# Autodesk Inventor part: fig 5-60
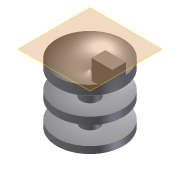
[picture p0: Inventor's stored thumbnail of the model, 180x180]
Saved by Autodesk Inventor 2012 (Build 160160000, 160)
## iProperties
Created: 2004-05
Part Number: fig 5-60
Document SubType Name: Modeling
Designer: CADCIM Technologies
Manufacturer: Standard
Standards Organization: Custom
Density: 1 g/cm^3
Material: Default
Author: CADCIM Technologies
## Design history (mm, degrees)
sketch "Sketch1"
  geometry: L1 (0.098, 22.743)-(0.098, 0.516); L2 (-3.621, 19.305)-(-3.621, 13.061); L3 (-3.621, 10.379)-(-3.621, 3.25); L4 (-3.664, 0.516)-(0.098, 0.516); L5 (-13.694, 4.7)-(-13.694, 1.836); L6 (-13.694, 26.851)-(-13.694, 23.014); L7 (-13.694, 15.335)-(-13.694, 12.343); A1 r 10.546 centre (-4.597, 32.185) between (-13.694, 26.851) and (0.098, 22.743); A2 r 21.828 centre (-4.597, 32.185) between (-13.694, 12.343) and (-3.621, 10.379); A3 r 12.918 centre (-4.597, 32.185) between (-13.694, 23.014) and (-3.621, 19.305); A4 r 19.149 centre (-4.597, 32.185) between (-13.694, 15.335) and (-3.621, 13.061); A5 r 28.952 centre (-4.597, 32.185) between (-13.694, 4.7) and (-3.621, 3.25); A6 r 31.683 centre (-4.597, 32.185) between (-13.694, 1.836) and (-3.664, 0.516)
  constraints: 14 end point, 12 point on circle, 6 centre point, 4 perpendicular, 2 parallel, 1 vertical
revolve "Revolution1" sketch "Sketch1" stored, may be unused: angle "d0" = 90 deg
workplane "Work Plane1"
sketch "Sketch2"
  geometry: L1 (3.408, -2.846)-(12.06, -2.846); L2 (12.06, -2.846)-(12.06, 2.873); L3 (12.06, 2.873)-(3.408, 2.873); L4 (3.408, 2.873)-(3.408, -2.846)
  constraints: 8 end point, 2 parallel, 1 horizontal, 1 perpendicular
extrude "Extrusion3" join sketch "Sketch2" stored distance "d8" = 10; taper "d9" = 0 deg
body "Solid1"
